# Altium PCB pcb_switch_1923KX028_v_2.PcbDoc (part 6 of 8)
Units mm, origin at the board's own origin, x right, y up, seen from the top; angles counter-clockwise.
Board outline 297.2 x 112.05 mm, 6 copper layers (Component Side, GND Layer 1, Inner Layer 1, Inner Layer 2, GND Layer 2, Solder Side), stack 1.578 mm thick; 545 components, 377 nets, 3174 pads, 1537 vias.
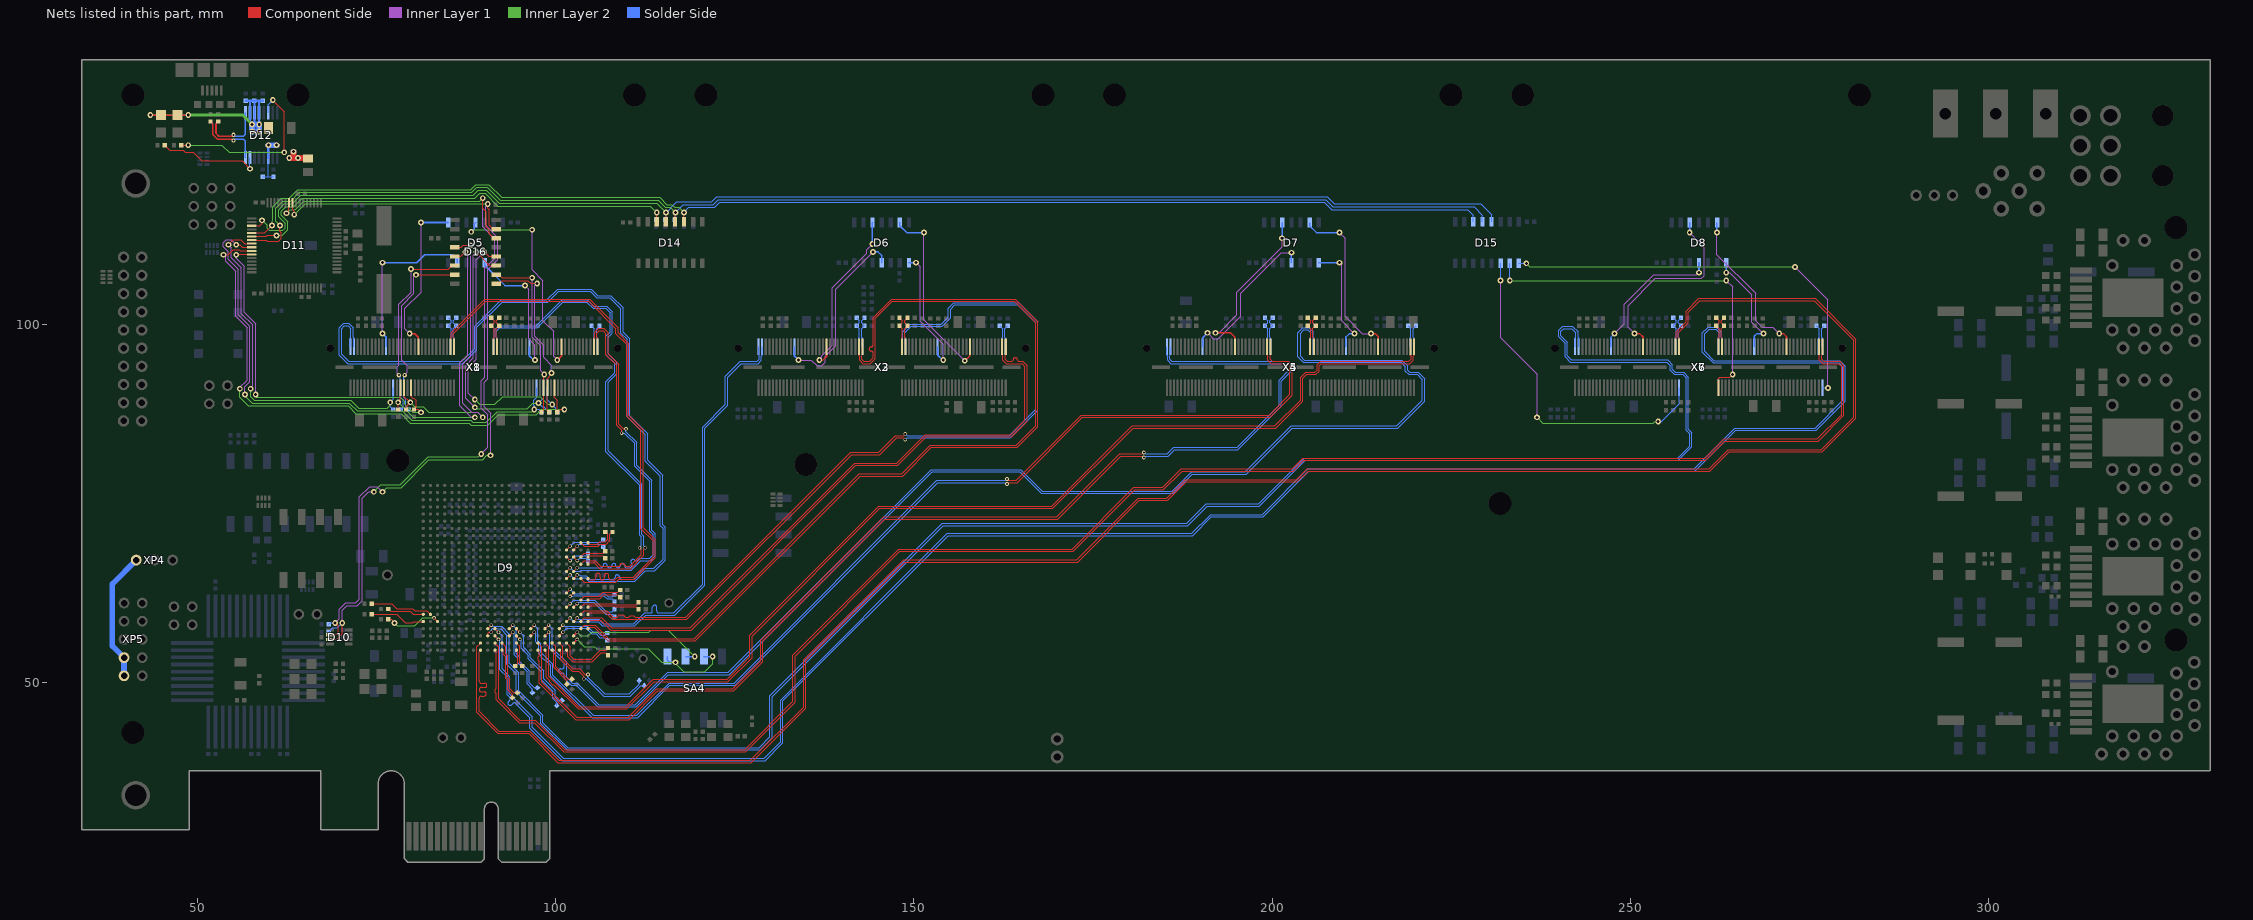
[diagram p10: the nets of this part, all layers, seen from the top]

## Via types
v1: diameter 0.8, hole 0.4, Component Side to Solder Side, tented both sides, 884 vias
v2: diameter 0.5, hole 0.3, Component Side to Solder Side, tented both sides, 269 vias
v3: diameter 1, hole 0.6, Component Side to Solder Side, tented both sides, 95 vias
v4: diameter 0.5/0.5/0.3/0.3/0.5/0.5 (per signal layer), hole 0.3, Component Side to Solder Side, tented both sides, 80 vias
v5: diameter 0.5/0.3/0.3/0.5/0.3/0.5 (per signal layer), hole 0.3, Component Side to Solder Side, tented both sides, 37 vias
v6: diameter 0.5/0.3/0.3/0.3/0.3/0.5 (per signal layer), hole 0.3, Component Side to Solder Side, tented both sides, 34 vias
v7: diameter 0.5/0.5/0.5/0.3/0.5/0.5 (per signal layer), hole 0.3, Component Side to Solder Side, tented both sides, 29 vias
v8: diameter 0.5, hole 0.3, Component Side to Solder Side, 25 vias
v9: diameter 0.5/0.3/0.5/0.3/0.3/0.5 (per signal layer), hole 0.3, Component Side to Solder Side, tented both sides, 25 vias
v10: diameter 0.5/0.5/0.3/0.5/0.5/0.5 (per signal layer), hole 0.3, Component Side to Solder Side, tented both sides, 19 vias
v11: diameter 0.6, hole 0.3, Component Side to Solder Side, tented both sides, 14 vias
v12: diameter 0.8, hole 0.5, Component Side to Solder Side, tented both sides, 11 vias
v13: diameter 0.5/0.3/0.5/0.5/0.3/0.5 (per signal layer), hole 0.3, Component Side to Solder Side, tented both sides, 7 vias
v14: diameter 0.8, hole 0.4, Component Side to Solder Side, 5 vias
v15: diameter 0.5/0.5/0.5/0.5/0.5/0.5 (per signal layer), hole 0.3, Component Side to Solder Side, tented both sides, 2 vias
v16: diameter 0.8, hole 0.5, Component Side to Solder Side, 1 vias

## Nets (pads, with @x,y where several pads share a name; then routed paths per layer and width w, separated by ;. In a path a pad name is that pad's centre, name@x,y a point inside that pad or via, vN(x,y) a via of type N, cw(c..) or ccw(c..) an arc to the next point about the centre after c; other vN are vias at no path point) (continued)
PHY_14_RST#: D15.3 X7.61 | length 47.1
  Inner Layer 1 w0.15: v1(231.9,106.1) 231.9,98.1 237,93 v1(237,87)
  Inner Layer 2 w0.15: v1(237,87) 237.8,86.2 253.2,86.2 253.419,86.419 v1(253.9,86.419)
  Solder Side w0.15: v1(231.9,106.1) 231.9,108.495 D15.3@231.905,108.5 ; v1(253.9,86.419) 254.319,86.419 256.81,88.91 X7.61@256.81,91.135
PHY_15_RST#: D15.2 X6.61 | length 49.6
  Component Side w0.15: X6.61@262.32,91.135 262.32,92.42 262.5,92.6 263.9,92.6 v1(264.3,93)
  Inner Layer 1 w0.15: v1(263.4,106.1) 264.3,105.2 v1(264.3,93)
  Inner Layer 2 w0.15: v1(233.2,106.1) v1(263.4,106.1)
  Solder Side w0.15: v1@233.175,106.125 D15.2@233.175,108.5
PHY_16_RST#: D15.1 X7.1 | length 58.4
  Inner Layer 1 w0.15: v1(273,108) 277.6,103.4 v1(277.6,91.1)
  Inner Layer 2 w0.15: v1(235.5,108.5) 236,108 v1(273,108)
  Solder Side w0.15: D15.1@234.445,108.5 v1(235.5,108.5) ; X7.1@276.815,91.135 276.85,91.1 v1(277.6,91.1)
PROG_3.3V: XP4.1 XP5.1 XP5.3 | length 18.2
  Solder Side w0.8: XP5.1@39.73,50.92 XP5.3@39.73,53.46 38.1,55.09 38.1,63.75 XP4.1@41.43,67.08
RCLK: D11.55 D14.12 D15.12 R119.2 | length 185
  Component Side w0.15: D11.55@57.55,111.75 59.55,111.75 59.7,111.6 61.3,111.6 61.7,112 61.7,112.8 61.5,113 v1(61.5,113.8) ; D14.12@116.635,114.3 116.7,114.365 v1(116.7,115.6)
  Inner Layer 2 w0.15: v1(61.5,113.8) 60.9,114.4 60.9,116.2 61.9,117.2 63,117.2 64.2,118.4 88.3,118.4 89,119.1 90.466,119.1 92.266,117.3 114.3,117.3 115.3,116.3 116,116.3 v1(116.7,115.6)
  Solder Side w0.15: R119.2@116.6,114.6 116.7,114.7 v1(116.7,115.6) 117.8,116.7 122,116.7 122.7,117.4 207.5,117.4 208.5,116.4 228.2,116.4 229.365,115.235 D15.12@229.365,114.3
RXLED#: D12.14 R11.2 | length 24.8
  Component Side w0.15: R11.2@47.7,125 v1(48.7,125) ; v1(60.5,131.3) 62.1,129.7 v1(62.1,124)
  Inner Layer 2 w0.15: v1(48.7,125) 53.4,125 54.4,124 v1(62.1,124)
  Solder Side w0.15: D12.14@59.852,129.524 59.852,130.653 v1(60.5,131.3)
SCL: D10.7 D11.42 D16.14 R176.1 | length 119
  Component Side w0.15: v1(62.4,115.5) 62.75,115.85 D11.42@62.75,116.95 ; D10.7@68.5,56 69.4,56 70.2,56.8 v1(70.2,58.3) ; v1(89.8,117.6) 89.8,116.2 90.3,115.7 90.3,113.6 90.7,113.2 90.7,112.6 91.295,112.005 D16.14@91.7,112.005
  Inner Layer 1 w0.15: v1(70.2,58.3) 70.2,60.1 70.8,60.7 72.3,60.7 73,61.4 73,75.7 73.9,76.6 v1(74.6,76.6) ; v1(89.6,81.9) 90.5,82.8 90.5,87.4 89.6,88.3 89.6,92.1 90.1,92.6 90.1,107.8 91.5,109.2 91.5,111.9 89.8,113.6 v1(89.8,117.6)
  Inner Layer 2 w0.15: v1(62.4,115.5) 62.9,116 63.6,116 64.8,117.2 89.4,117.2 v1(89.8,117.6) ; v1(74.6,76.6) 75.6,77.6 78.3,77.6 82.2,81.5 89.2,81.5 v1(89.6,81.9)
  Solder Side w0.15: R176.1@68.3,57 68.9,57.6 69.5,57.6 v1(70.2,58.3)
SDA: D10.6 D11.41 D16.15 R177.1 | length 115.6
  Component Side w0.15: D11.41@63.25,116.95 63.25,116 63.5,115.75 v1(63.5,115.3) ; D10.6@68.5,56.65 69.35,56.65 69.6,56.9 69.6,57.9 v1(69.2,58.3) ; v1(90.5,116.8) 90.5,116.2 90.7,116 90.7,113.8 91.225,113.275 D16.15@91.7,113.275
  Inner Layer 1 w0.15: v1(69.2,58.3) 69.8,58.9 69.8,60.2 70.7,61.1 72.1,61.1 72.6,61.6 72.6,75.9 74,77.3 75.1,77.3 v1(75.8,76.6) ; v1(90.5,116.8) 90.2,116.5 90.2,113.8 91.9,112.1 91.9,109 90.5,107.6 90.5,92.4 90,91.9 90,88.5 90.9,87.6 v1(90.9,81.7)
  Inner Layer 2 w0.15: v1(63.5,115.3) 65,116.8 v1(90.5,116.8) ; v1(75.8,76.6) 76.4,77.2 78.4,77.2 82.3,81.1 89.8,81.1 90.4,81.7 v1(90.9,81.7)
  Solder Side w0.15: R177.1@68.3,58.1 68.5,58.3 v1(69.2,58.3)
SGMII_L0DATI_0_N: C81.2 D9.J23 | length 5.9
  Component Side w0.15: D9.J23@103.5,69.5 104.01,68.99 105.928,68.99 106.238,69.3 107.038,69.3 107.565,69.827 107.565,70.655 C81.2@107.91,71
SGMII_L0DATI_0_P: C80.2 D9.J24 | length 4.3
  Component Side w0.15: D9.J24@104.5,69.5 104.7,69.3 105.8,69.3 106.11,69.61 106.91,69.61 107.255,69.955 107.255,70.655 C80.2@106.91,71
SGMII_L0DATI_1_N: C84.2 D9.K21 | length 5.7
  Component Side w0.15: D9.K21@101.5,68.5 v5(102,69)
  Solder Side w0.15: v5(102,69) 102.562,69.562 106.289,69.562 C84.2@106.629,69.902
SGMII_L0DATI_1_P: C82.2 D9.K22 | length 4.6
  Component Side w0.15: D9.K22@102.5,68.5 v5(103,69)
  Solder Side w0.15: v5(103,69) 103.252,69.252 106.289,69.252 C82.2@106.629,68.912
SGMII_L0DATI_2_N: C185.2 D9.L23 | length 3.7
  Component Side w0.15: D9.L23@103.5,67.5 104.01,68.01 105.11,68.01 106.585,68.01 C185.2@106.9,68.325
SGMII_L0DATI_2_P: C186.2 D9.L24 | length 2.6
  Component Side w0.15: D9.L24@104.5,67.5 104.7,67.7 106.525,67.7 C186.2@106.9,67.325
SGMII_L0DATI_3_N: C191.2 D9.L21 | length 3.6
  Component Side w0.15: D9.L21@101.5,67.5 v6(102,67)
  Solder Side w0.15: v6(102,67) 102.655,67.655 104.155,67.655 C191.2@104.5,68
SGMII_L0DATI_3_P: C192.2 D9.L22 | length 2.5
  Component Side w0.15: D9.L22@102.5,67.5 v6(103,67)
  Solder Side w0.15: v6(103,67) 103.345,67.345 104.155,67.345 C192.2@104.5,67
SGMII_L0DATO_0_N: D9.P23 X1.58 | length 75.2
  Component Side w0.15: X1.58@85.315,96.865 85.315,98.09 85.41,98.185 85.41,98.828 90.082,103.5 104.738,103.5 108.71,99.528 108.71,98.8 110.2,97.31 110.2,87.3 112.2,85.3 112.2,71.6 113.91,69.89 113.91,67.372 110.928,64.39 108.79,64.39 108.39,63.99 104.01,63.99 D9.P23@103.5,64.5
SGMII_L0DATO_0_P: D9.P24 X1.60 | length 75.2
  Component Side w0.15: X1.60@85.815,96.865 85.815,98.09 85.72,98.185 85.72,98.7 90.21,103.19 104.61,103.19 108.4,99.4 108.4,98.672 109.89,97.182 109.89,87.172 111.89,85.172 111.89,71.472 113.6,69.762 113.6,67.5 110.8,64.7 108.662,64.7 108.262,64.3 107.7,64.3 cw(c107.7,64.6) 107.4,64.6 107.4,64.9 ccw(c107.1,64.9) 106.8,64.9 106.8,64.6 cw(c106.5,64.6) 106.5,64.3 cw(c106.5,64.6) 106.2,64.6 106.2,64.95 ccw(c105.9,64.95) 105.6,64.95 105.6,64.6 cw(c105.3,64.6) 105.3,64.3 104.7,64.3 D9.P24@104.5,64.5
SGMII_L0DATO_1_N: D9.P22 X8.118 | length 108
  Component Side w0.15: D9.P22@102.5,64.5 v6(103,65)
  Solder Side w0.15: X8.118@71.81,96.865 71.81,98.09 71.715,98.185 71.715,99.523 71.128,100.11 70.372,100.11 69.79,99.528 69.79,95.672 70.972,94.49 87.028,94.49 89,96.462 89,99.562 92.538,103.1 98.9,103.1 100.4,104.6 104.8,104.6 105.7,103.7 107.562,103.7 109.1,102.162 109.1,98.762 109.99,97.872 109.99,87.11 112.5,84.6 112.5,80.9 114.6,78.8 114.6,71.9 115,71.5 115,67.2 113.71,65.91 112.372,65.91 110.872,64.41 109.2,64.41 cw(c109.2,64.71) 108.9,64.71 108.9,64.714 ccw(c108.6,64.714) 108.3,64.714 108.3,64.71 cw(c108,64.71) 108,64.41 104.723,64.41 104.228,64.905 103.395,64.905 103.3,65 v6(103,65)
SGMII_L0DATO_1_P: D9.P21 X8.120 | length 108
  Component Side w0.15: D9.P21@101.5,64.5 v6(102,65)
  Solder Side w0.15: X8.120@71.31,96.865 71.31,98.09 71.405,98.185 71.405,99.395 71,99.8 70.5,99.8 70.1,99.4 70.1,95.8 71.1,94.8 86.9,94.8 88.69,96.59 88.69,99.69 92.41,103.41 98.772,103.41 100.272,104.91 104.928,104.91 105.828,104.01 107.69,104.01 109.41,102.29 109.41,98.89 110.3,98 110.3,87.238 112.81,84.728 112.81,81.028 114.91,78.928 114.91,72.028 115.31,71.628 115.31,67.072 113.838,65.6 112.5,65.6 111,64.1 104.595,64.1 104.1,64.595 103.395,64.595 103.3,64.5 102.5,64.5 v6(102,65)
SGMII_L0DATO_2_N: D9.N21 X1.118 | length 52.2
  Component Side w0.15: D9.N21@101.5,65.5 v6(102,66) ; X1.118@105.32,96.865 105.32,98.09 105.415,98.185 105.415,98.853 105.972,99.41 106.728,99.41 107.31,98.828 107.31,95.9 108.8,94.41 108.8,86.019 109.419,85.4 v8(109.8,85.4)
  Solder Side w0.15: v6(102,66) 102.5,65.5 103.4,65.5 103.59,65.69 110.528,65.69 111.838,67 113.238,67 113.91,67.672 113.91,70.728 113.41,71.228 113.41,78.228 111.31,80.328 111.31,83.509 109.8,85.019 v8(109.8,85.4)
SGMII_L0DATO_2_P: D9.N22 X1.120 | length 52.2
  Component Side w0.15: D9.N22@102.5,65.5 v6(103,66) ; X1.120@105.82,96.865 105.82,98.09 105.725,98.185 105.725,98.725 106.1,99.1 106.6,99.1 107,98.7 107,95.772 108.49,94.282 108.49,85.891 109.2,85.181 v8(109.2,84.8)
  Solder Side w0.15: v6(103,66) 106.3,66 ccw(c106.3,66.3) 106.6,66.3 cw(c106.9,66.3) 106.9,66.6 cw(c106.9,66.3) 107.2,66.3 ccw(c107.5,66.3) 107.5,66 ccw(c107.5,66.3) 107.8,66.3 cw(c108.1,66.3) 108.1,66.6 cw(c108.1,66.3) 108.4,66.3 ccw(c108.7,66.3) 108.7,66 ccw(c108.7,66.3) 109,66.3 cw(c109.3,66.3) 109.3,66.6 cw(c109.3,66.3) 109.6,66.3 ccw(c109.9,66.3) 109.9,66 110.4,66 110.6,66.2 ccw(c110.388,66.412) 110.6,66.624 110.57,66.654 cw(c110.782,66.866) 110.57,67.079 cw(c110.782,66.866) 110.994,67.079 111.024,67.049 ccw(c111.236,67.261) 111.449,67.049 111.71,67.31 113.11,67.31 113.6,67.8 113.6,70.6 113.1,71.1 113.1,78.1 111,80.2 111,83.381 109.581,84.8 v8(109.2,84.8)
SGMII_L0DATO_3_N: D9.M23 X8.58 | length 67.7
  Component Side w0.15: D9.M23@103.5,66.5 104.01,67.01 105.49,67.01 106.29,66.21 108.82,66.21 ccw(c108.82,66.4) 109.01,66.4 cw(c109.184,66.4) 109.184,66.574 109.436,66.574 cw(c109.436,66.4) 109.61,66.4 ccw(c109.8,66.4) 109.8,66.21 110.31,66.21 111.945,67.845 111.945,68.555 v8(111.7,68.8)
  Solder Side w0.15: X8.58@91.815,96.865 91.815,98.09 91.72,98.185 91.72,99.02 92.2,99.5 97.4,99.5 101,103.1 104.3,103.1 105.2,102.2 107,102.2 107.6,101.6 107.6,98.9 107,98.3 107,95.762 108.2,94.562 108.2,93.2 107,92 107,82.2 111.7,77.5 111.7,70.545 111.945,70.3 111.945,69.045 v8(111.7,68.8)
SGMII_L0DATO_3_P: D9.M24 X8.60 | length 67.7
  Component Side w0.15: D9.M24@104.5,66.5 104.7,66.7 105.362,66.7 106.162,65.9 110.438,65.9 112.255,67.717 112.255,68.555 v8(112.5,68.8)
  Solder Side w0.15: X8.60@91.315,96.865 91.315,98.09 91.41,98.185 91.41,99.148 92.072,99.81 97.272,99.81 100.872,103.41 104.428,103.41 105.328,102.51 107.128,102.51 107.91,101.728 107.91,98.772 107.31,98.172 107.31,95.89 108.51,94.69 108.51,93.072 107.31,91.872 107.31,82.328 112.01,77.628 112.01,70.673 112.255,70.428 112.255,69.045 v8(112.5,68.8)
SGMII_L1DATI_0_N: C89.2 D9.T21 | length 7.5
  Component Side w0.15: D9.T21@101.5,62.5 v6(102,63)
  Solder Side w0.15: v6@102,63 102.595,62.405 106.85,62.405 107.3,61.955 107.855,61.955 C89.2@108.2,62.3
SGMII_L1DATI_0_P: C87.2 D9.T22 | length 7.3
  Component Side w0.15: v6(102,62) D9.T22@102.5,62.5
  Solder Side w0.15: v6(102,62) 102.4,62 102.495,62.095 106.722,62.095 107.172,61.645 107.855,61.645 C87.2@108.2,61.3
SGMII_L1DATI_1_N: C62.2 D9.V23 | length 8.5
  Component Side w0.15: D9.V23@103.5,60.5 104.01,61.01 108.19,61.01 108.357,60.843 111.219,60.843 C62.2@111.559,61.183
SGMII_L1DATI_1_P: C60.2 D9.V24 | length 7.4
  Component Side w0.15: D9.V24@104.5,60.5 104.7,60.7 108.062,60.7 108.229,60.533 111.219,60.533 C60.2@111.559,60.193
SGMII_L1DATI_2_N: C93.2 D9.U23 | length 6.1
  Component Side w0.15: D9.U23@103.5,61.5 104.01,62.01 106.005,62.01 106.55,62.555 108.655,62.555 C93.2@109,62.9
SGMII_L1DATI_2_P: C91.2 D9.U24 | length 5
  Component Side w0.15: D9.U24@104.5,61.5 104.7,61.7 106.133,61.7 106.678,62.245 108.655,62.245 C91.2@109,61.9
SGMII_L1DATI_3_N: C68.2 D9.V21 | length 7.9
  Component Side w0.15: D9.V21@101.5,60.5 v6(102,61)
  Solder Side w0.15: v6(102,61) 102.5,61.5 105.428,61.5 107.073,59.855 107.855,59.855 C68.2@108.2,60.2
SGMII_L1DATI_3_P: C67.2 D9.V22 | length 6.8
  Component Side w0.15: D9.V22@102.5,60.5 v6(103,61)
  Solder Side w0.15: v6(103,61) 103.19,61.19 105.3,61.19 106.945,59.545 107.855,59.545 C67.2@108.2,59.2
SGMII_L1DATO_0_N: D9.AA23 X2.58 | length 126.1
  Component Side w0.15: D9.AA23@103.5,57.5 104.01,58.01 105.49,58.01 107.39,56.11 119.362,56.11 142.362,79.11 148.31,79.11 152.31,83.11 164.31,83.11 167,85.8 167,100.2 164,103.2 147,103.2 144.61,100.81 144.61,95.172 143.928,94.49 142.892,94.49 142.41,94.972 142.41,95.545 142.315,95.64 X2.58@142.315,96.865
SGMII_L1DATO_0_P: D9.AA24 X2.60 | length 126.1
  Component Side w0.15: D9.AA24@104.5,57.5 104.7,57.7 105.362,57.7 107.262,55.8 119.49,55.8 142.49,78.8 148.438,78.8 152.438,82.8 164.438,82.8 167.31,85.672 167.31,100.328 164.128,103.51 146.872,103.51 144.3,100.938 144.3,97.1 cw(c144.05,97.1) 144.05,96.85 144.028,96.85 ccw(c144.028,96.6) 143.778,96.6 143.778,96.5 ccw(c144.028,96.5) 144.028,96.25 144.05,96.25 cw(c144.05,96) 144.3,96 144.3,95.3 143.8,94.8 143.02,94.8 142.72,95.1 142.72,95.545 142.815,95.64 X2.60@142.815,96.865
SGMII_L1DATO_1_N: D9.Y21 X3.118 | length 60.3
  Component Side w0.15: D9.Y21@101.5,58.5 v6(102,59)
  Solder Side w0.15: v6(102,59) 102.4,58.6 102.51,58.49 105.9,58.49 106.49,57.9 111.038,57.9 112.528,59.39 116.628,59.39 120.82,63.582 120.82,85.492 124,88.672 124,92.6 125.89,94.49 128.233,94.49 128.715,94.972 128.715,95.545 128.81,95.64 X3.118@128.81,96.865
SGMII_L1DATO_1_P: D9.Y22 X3.120 | length 60.3
  Component Side w0.15: D9.Y22@102.5,58.5 v6(103,59)
  Solder Side w0.15: v6(103,59) 103.2,58.8 106.028,58.8 106.618,58.21 110.91,58.21 112.4,59.7 113.2,59.7 ccw(c113.2,60) 113.5,60 113.5,60.478 cw(c113.8,60.478) 113.8,60.778 cw(c113.8,60.478) 114.1,60.478 114.1,60 ccw(c114.4,60) 114.4,59.7 116.5,59.7 120.51,63.71 120.51,85.62 123.69,88.8 123.69,92.728 125.762,94.8 128.105,94.8 128.405,95.1 128.405,95.545 128.31,95.64 X3.120@128.31,96.865
SGMII_L1DATO_2_N: D9.Y23 X2.118 | length 87.7
  Component Side w0.15: D9.Y23@103.5,58.5 104.01,59.01 106.423,59.01 107.823,57.61 118.772,57.61 141.772,80.61 147.61,80.61 151.6,84.6 163.5,84.6 165.5,86.6 165.5,94.09 165.1,94.49 162.897,94.49 162.415,94.972 162.415,95.545 162.32,95.64 X2.118@162.32,96.865
SGMII_L1DATO_2_P: D9.Y24 X2.120 | length 87.7
  Component Side w0.15: D9.Y24@104.5,58.5 104.7,58.7 106.295,58.7 107.695,57.3 118.9,57.3 141.9,80.3 147.738,80.3 151.728,84.29 163.628,84.29 165.81,86.472 165.81,94.218 165.228,94.8 164.7,94.8 cw(c164.7,95.05) 164.45,95.05 164.45,95.072 ccw(c164.2,95.072) 164.2,95.322 164.1,95.322 ccw(c164.1,95.072) 163.85,95.072 163.85,95.05 cw(c163.6,95.05) 163.6,94.8 163.025,94.8 162.725,95.1 162.725,95.545 162.82,95.64 X2.120@162.82,96.865
SGMII_L1DATO_3_N: D9.W23 X3.58 | length 112.5
  Component Side w0.15: D9.W23@103.5,59.5 104.01,60.01 107.127,60.01 108.027,59.11 108.58,59.11 108.89,59.42 109.39,59.42 109.7,59.11 110.2,59.11 110.39,59.3 110.89,59.3 111.08,59.11 118.172,59.11 141.172,82.11 145.11,82.11 147.4,84.4 ; 147.364,84.364 147.455,84.455 148.555,84.455 v8(148.8,84.7)
  Solder Side w0.15: v8(148.8,84.7) 149.045,84.455 163.317,84.455 167,88.138 167,100.2 164.5,102.7 155.71,102.7 155.11,102.1 155.11,100.882 153.928,99.7 149.62,99.7 148.72,98.8 148.72,98.185 148.815,98.09 X3.58@148.815,96.865
SGMII_L1DATO_3_P: D9.W24 X3.60 | length 112.4
  Component Side w0.15: D9.W24@104.5,59.5 104.7,59.7 106.999,59.7 107.899,58.8 118.3,58.8 141.3,81.8 145.238,81.8 147.583,84.145 148.555,84.145 v8(148.8,83.9)
  Solder Side w0.15: X3.60@148.315,96.865 148.315,98.09 148.41,98.185 148.41,98.928 149.492,100.01 153.8,100.01 154.8,101.01 154.8,102.228 155.582,103.01 164.628,103.01 167.31,100.328 167.31,88.01 163.445,84.145 149.045,84.145 v8(148.8,83.9)
SGMII_L2DATI_0_N: C79.2 D9.AC21 | length 8.2
  Component Side w0.15: D9.AC21@101.5,55.5 102.01,54.99 102.01,53.7 102.51,53.2 104.962,53.2 106.217,54.455 106.955,54.455 C79.2@107.3,54.8
SGMII_L2DATI_0_P: C77.2 D9.AD21 | length 7.6
  Component Side w0.15: D9.AD21@101.5,54.5 101.7,54.3 101.7,53.572 102.382,52.89 105.09,52.89 106.345,54.145 106.955,54.145 C77.2@107.3,53.8
SGMII_L2DATI_1_N: C73.2 D9.AA20 | length 7.6
  Component Side w0.15: D9.AA20@100.5,57.5 v6(101,58)
  Solder Side w0.15: v6(101,58) 101.165,57.835 104.403,57.835 105.138,57.1 105.755,57.1 106.3,56.555 106.855,56.555 C73.2@107.2,56.9
SGMII_L2DATI_1_P: C72.2 D9.AB20 | length 7.8
  Component Side w0.15: D9.AB20@100.5,56.5 v6(101,57)
  Solder Side w0.15: v6(101,57) 101.525,57.525 104.275,57.525 105.01,56.79 105.627,56.79 106.172,56.245 106.855,56.245 C72.2@107.2,55.9
SGMII_L2DATI_2_N: C97.2 D9.AC20 | length 16.3
  Component Side w0.15: D9.AC20@100.5,55.5 101.01,54.99 101.01,54.19 101.01,53.295 102.405,51.9 103.319,51.9 104.119,51.1 v8(104.5,51.1)
  Solder Side w0.15: v8(104.5,51.1) 104.5,50.719 106.819,48.4 110.281,48.4 111.646,49.766 C97.2@111.646,50.246
SGMII_L2DATI_2_P: C98.2 D9.AD20 | length 16
  Component Side w0.15: D9.AD20@100.5,54.5 100.7,54.3 100.7,53.167 102.277,51.59 103.191,51.59 103.9,50.881 v8(103.9,50.5)
  Solder Side w0.15: v8(103.9,50.5) 104.281,50.5 106.691,48.09 110.409,48.09 111.866,49.546 C98.2@112.346,49.546
SGMII_L2DATI_3_N: C64.2 D9.AC19 | length 6.5
  Component Side w0.15: D9.AC19@99.5,55.5 100.01,54.99 100.01,52.209 101.766,50.454 C64.2@102.246,50.454
SGMII_L2DATI_3_P: C76.2 D9.AD19 | length 5.6
  Component Side w0.15: D9.AD19@99.5,54.5 99.7,54.3 99.7,52.081 101.546,50.234 C76.2@101.546,49.754
SGMII_L2DATO_0_N: D9.AA16 X4.58 | length 142
  Component Side w0.15: D9.AA16@96.5,57.5 v6(97,58) ; v8(163,78.4) 163.195,78.205 164.3,78.205 173.395,87.3 199.6,87.3 202.5,90.2 202.5,94.09 202.1,94.49 199.892,94.49 199.41,94.972 199.41,95.545 199.315,95.64 X4.58@199.315,96.865
  Solder Side w0.15: v6(97,58) 97.5,57.5 97.5,55.8 97.91,55.39 97.91,54.2 99.61,52.5 99.61,50.99 105.2,45.4 111.3,45.4 115.81,49.91 124.9,49.91 153.195,78.205 162.805,78.205 v8(163,78.4)
SGMII_L2DATO_0_P: D9.AB16 X4.60 | length 142
  Component Side w0.15: D9.AB16@96.5,56.5 v6(97,57) ; v8(163,77.7) 163.195,77.895 164.428,77.895 173.523,86.99 199.728,86.99 202.81,90.072 202.81,94.218 202.228,94.8 200.02,94.8 199.72,95.1 199.72,95.545 199.815,95.64 X4.60@199.815,96.865
  Solder Side w0.15: v6(97,57) 97.19,56.81 97.19,55.672 97.6,55.262 97.6,54.072 98,53.672 98,53.498 98.361,53.137 98.535,53.137 99.3,52.372 99.3,50.862 105.072,45.09 111.428,45.09 115.938,49.6 125.028,49.6 153.323,77.895 162.805,77.895 v8(163,77.7)
SGMII_L2DATO_1_N: D9.AD17 X5.118 | length 156.1
  Component Side w0.15: D9.AD17@97.5,54.5 97.7,54.3 97.7,53.7 97.58,53.58 97.58,53.08 97.7,52.96 97.7,49.862 102.772,44.79 110.228,44.79 114.238,48.8 124.838,48.8 128.91,52.872 128.91,55.772 145.938,72.8 170.1,72.8 178.895,81.595 181.905,81.595 v8(182.1,81.4)
  Solder Side w0.15: v8(182.1,81.4) 182.295,81.595 185.505,81.595 186.41,82.5 195.238,82.5 201.31,88.572 201.31,92.072 202.81,93.572 202.81,94.228 202.238,94.8 186.015,94.8 185.715,95.1 185.715,95.545 185.81,95.64 X5.118@185.81,96.865
SGMII_L2DATO_1_P: D9.AC17 X5.120 | length 156.1
  Component Side w0.15: D9.AC17@97.5,55.5 98.01,54.99 98.01,49.99 102.9,45.1 110.1,45.1 114.11,49.11 124.71,49.11 128.6,53 128.6,55.9 145.81,73.11 169.972,73.11 178.767,81.905 181.905,81.905 v8(182.1,82.1)
  Solder Side w0.15: v8(182.1,82.1) 182.295,81.905 185.377,81.905 186.282,82.81 195.11,82.81 201,88.7 201,92.2 202.5,93.7 202.5,94.1 202.11,94.49 185.887,94.49 185.405,94.972 185.405,95.545 185.31,95.64 X5.120@185.31,96.865
SGMII_L2DATO_2_N: D9.AC18 X4.118 | length 153
  Component Side w0.15: D9.AC18@98.5,55.5 99.01,54.99 99.01,50.828 103.238,46.6 109.8,46.6 113.61,50.41 123.91,50.41 127.1,53.6 127.1,56.6 145.11,74.61 169.272,74.61 180.462,85.8 200.4,85.8 203.99,89.39 203.99,92.59 204.7,93.3 205.99,93.3 206.29,93.6 206.29,94.318 206.772,94.8 219.115,94.8 219.415,95.1 219.415,95.545 219.32,95.64 X4.118@219.32,96.865
SGMII_L2DATO_2_P: D9.AD18 X4.120 | length 153
  Component Side w0.15: D9.AD18@98.5,54.5 98.7,54.3 98.7,50.7 99.165,50.235 99.165,50.061 99.526,49.7 99.7,49.7 103.11,46.29 109.928,46.29 113.738,50.1 124.038,50.1 127.41,53.472 127.41,56.472 145.238,74.3 169.4,74.3 180.59,85.49 200.528,85.49 204.3,89.262 204.3,92.462 204.828,92.99 206.118,92.99 206.6,93.472 206.6,94.19 206.9,94.49 219.243,94.49 219.725,94.972 219.725,95.545 219.82,95.64 X4.120@219.82,96.865
SGMII_L2DATO_3_N: D9.AA18 X5.58 | length 180.3
  Component Side w0.15: D9.AA18@98.5,57.5 v6(99,58)
  Solder Side w0.15: v6(99,58) 99.5,57.5 99.5,54.8 101.5,52.8 101.5,50.7 102.3,49.9 103,49.9 106,46.9 111.1,46.9 115.6,51.4 124.09,51.4 152.4,79.71 164.89,79.71 167.9,76.7 186.062,76.7 188.762,79.4 196.272,79.4 202.672,85.8 217.4,85.8 221,89.4 221,92.262 220.272,92.99 219.082,92.99 218.6,93.472 218.6,94.09 218,94.69 204.372,94.69 203.59,95.472 203.59,98.828 204.272,99.51 205.138,99.51 205.72,98.928 205.72,98.185 205.815,98.09 X5.58@205.815,96.865
SGMII_L2DATO_3_P: D9.AB18 X5.60 | length 180.3
  Component Side w0.15: D9.AB18@98.5,56.5 v6(99,57)
  Solder Side w0.15: v6(99,57) 99.19,56.81 99.19,54.672 101.19,52.672 101.19,52.2 cw(c100.89,52.2) 100.89,51.9 100.668,51.9 ccw(c100.668,51.6) 100.368,51.6 ccw(c100.668,51.6) 100.668,51.3 100.89,51.3 cw(c100.89,51) 101.19,51 101.19,50.572 102.172,49.59 102.872,49.59 105.872,46.59 111.228,46.59 115.728,51.09 124.218,51.09 152.528,79.4 164.762,79.4 167.772,76.39 186.19,76.39 188.89,79.09 196.4,79.09 202.8,85.49 217.528,85.49 221.31,89.272 221.31,92.39 220.4,93.3 219.21,93.3 218.91,93.6 218.91,94.218 218.128,95 216.7,95 204.5,95 203.9,95.6 203.9,98.7 204.4,99.2 205.01,99.2 205.41,98.8 205.41,98.185 205.315,98.09 X5.60@205.315,96.865
SGMII_L3DATI_0_N: C49.2 D9.AC14 | length 3.5
  Component Side w0.15: D9.AC14@94.5,55.5 94.98,55.02 94.98,52.645 C49.2@95.325,52.3
SGMII_L3DATI_0_P: C48.2 D9.AD14 | length 2.4
  Component Side w0.15: C48.2@94.325,52.3 94.67,52.645 94.67,54.23 94.5,54.4 D9.AD14@94.5,54.5
SGMII_L3DATI_1_N: C55.2 D9.AA14 | length 13
  Component Side w0.15: D9.AA14@94.5,57.5 v6(95,57)
  Solder Side w0.15: v6(95,57) 95.5,56.5 95.5,54.9 96.46,53.94 96.46,53.44 98.3,51.6 98.3,51.472 ; 98.3,51.5 98.3,50.5 99.9,48.9 99.9,47.919 100.366,47.454 C55.2@100.846,47.454
SGMII_L3DATI_1_P: C54.2 D9.AB14 | length 12.1
  Component Side w0.15: D9.AB14@94.5,56.5 v6(95,56)
  Solder Side w0.15: v6(95,56) 95.19,55.81 95.19,54.772 96.15,53.812 96.15,53.312 97.99,51.472 97.99,50.372 99.59,48.772 99.59,47.791 100.146,47.234 C54.2@100.146,46.754
SGMII_L3DATI_2_N: C88.2 D9.AA13 | length 11.2
  Component Side w0.15: D9.AA13@93.5,57.5 v6(94,58)
  Solder Side w0.15: v6(94,58) 94.5,57.5 94.5,54 95,53.5 95,52.9 96.3,51.6 96.3,49.919 96.966,49.254 C88.2@97.446,49.254
SGMII_L3DATI_2_P: C86.2 D9.AB13 | length 10.3
  Component Side w0.15: D9.AB13@93.5,56.5 v6(94,57)
  Solder Side w0.15: v6(94,57) 94.19,56.81 94.19,53.872 94.69,53.372 94.69,52.772 95.99,51.472 95.99,49.791 96.746,49.034 C86.2@96.746,48.554
SGMII_L3DATI_3_N: C92.2 D9.AC12 | length 8.1
  Component Side w0.15: D9.AC12@92.5,55.5 93.01,54.99 93.01,54.028 93.31,53.728 93.31,50.7 93.61,50.4 93.61,49.109 94.166,48.554 C92.2@94.646,48.554
SGMII_L3DATI_3_P: C90.2 D9.AD12 | length 7.2
  Component Side w0.15: D9.AD12@92.5,54.5 92.7,54.3 92.7,53.9 93,53.6 93,50.572 93.3,50.272 93.3,48.981 93.946,48.334 C90.2@93.946,47.854
SGMII_L3DATO_0_N: D9.AC9 X6.58 | length 272.5
  Component Side w0.15: D9.AC9@89.5,55.5 88.99,54.99 88.99,45.81 91.91,42.89 96.21,42.89 100.31,38.79 127.29,38.79 134.91,46.41 134.91,53.01 148.7,66.8 172.838,66.8 181.438,75.4 185.438,75.4 188.038,78 203.538,78 205.028,79.49 261.128,79.49 263.828,82.19 276.828,82.19 281.51,86.872 281.51,97.928 275.828,103.61 259.582,103.61 257.8,101.828 257.8,100.318 256.41,98.928 256.41,98.185 256.315,98.09 X6.58@256.315,96.865
SGMII_L3DATO_0_P: D9.AD9 X6.60 | length 272.5
  Component Side w0.15: D9.AD9@89.5,54.5 89.3,54.3 89.3,50.2 ccw(c89.6,50.2) 89.6,49.9 90.1,49.9 cw(c90.1,49.6) 90.4,49.6 cw(c90.1,49.6) 90.1,49.3 89.6,49.3 ccw(c89.6,49) 89.3,49 ccw(c89.6,49) 89.6,48.7 90.007,48.7 cw(c90.007,48.4) 90.306,48.4 cw(c90.007,48.4) 90.007,48.1 89.6,48.1 ccw(c89.6,47.8) 89.3,47.8 89.3,45.938 92.038,43.2 96.338,43.2 100.438,39.1 127.162,39.1 134.6,46.538 134.6,53.138 148.572,67.11 172.71,67.11 181.31,75.71 185.31,75.71 187.91,78.31 203.41,78.31 204.9,79.8 261,79.8 263.7,82.5 276.7,82.5 281.2,87 281.2,97.8 275.7,103.3 259.71,103.3 258.11,101.7 258.11,100.19 256.72,98.8 256.72,98.185 256.815,98.09 X6.60@256.815,96.865
SGMII_L3DATO_1_N: D9.AA10 X7.118 | length 238
  Component Side w0.15: D9.AA10@90.5,57.5 v6(91,58)
  Solder Side w0.15: v6(91,58) 91.19,57.81 92.428,57.81 93.5,56.738 93.5,52.638 94.81,51.328 94.81,48.828 98.21,45.428 98.21,44.39 101.7,40.9 128.4,40.9 129.9,42.4 129.9,48.138 153.972,72.21 188.11,72.21 190.81,74.91 198.11,74.91 204.51,81.31 256.61,81.31 258.3,83 258.3,84.7 257.8,85.2 257.8,92.5 257.31,92.99 256.172,92.99 255.59,93.572 255.59,94.2 255.09,94.7 241.662,94.7 240.9,95.462 240.9,97.362 239.99,98.272 239.99,99.128 240.572,99.71 241.933,99.71 242.715,98.928 242.715,98.185 242.81,98.09 X7.118@242.81,96.865
SGMII_L3DATO_1_P: D9.AB10 X7.120 | length 238
  Component Side w0.15: D9.AB10@90.5,56.5 90.5,56.775 cw(c90.725,56.775) 90.725,57 v6(91,57)
  Solder Side w0.15: v6(91,57) 91,57.25 cw(c91.25,57.25) 91.25,57.5 92.3,57.5 93.19,56.61 93.19,52.51 94.5,51.2 94.5,48.7 97.9,45.3 97.9,44.262 101.572,40.59 128.528,40.59 130.21,42.272 130.21,48.01 154.1,71.9 188.238,71.9 190.938,74.6 198.238,74.6 204.638,81 256.738,81 258.61,82.872 258.61,84.828 258.11,85.328 258.11,91.1 258.11,92.628 257.438,93.3 256.3,93.3 255.9,93.7 255.9,94.328 255.218,95.01 241.79,95.01 241.21,95.59 241.21,97.49 240.3,98.4 240.3,99 240.7,99.4 241.805,99.4 242.405,98.8 242.405,98.185 242.31,98.09 X7.120@242.31,96.865
SGMII_L3DATO_2_N: D9.AC11 X6.118 | length 233.7
  Component Side w0.15: D9.AC11@91.5,55.5 92.01,54.99 92.01,47.69 95,44.7 97.138,44.7 101.238,40.6 126.362,40.6 133.1,47.338 133.1,53.8 147.91,68.61 172.11,68.61 180.71,77.21 184.71,77.21 187.31,79.81 202.81,79.81 204.31,81.31 260.41,81.31 263.1,84 276.1,84 279.5,87.4 279.5,94.09 279.1,94.49 276.897,94.49 276.415,94.972 276.415,95.545 276.32,95.64 X6.118@276.32,96.865
SGMII_L3DATO_2_P: D9.AD11 X6.120 | length 233.7
  Component Side w0.15: D9.AD11@91.5,54.5 91.7,54.3 91.7,49.2 91.577,49.077 91.577,48.567 91.7,48.444 91.7,47.562 94.872,44.39 97.01,44.39 101.11,40.29 126.49,40.29 133.41,47.21 133.41,53.672 148.038,68.3 172.238,68.3 180.838,76.9 184.838,76.9 187.438,79.5 202.938,79.5 204.438,81 260.538,81 263.228,83.69 276.228,83.69 279.81,87.272 279.81,94.218 279.228,94.8 277.025,94.8 276.725,95.1 276.725,95.545 276.82,95.64 X6.120@276.82,96.865
SGMII_L3DATO_3_N: D9.AA11 X7.58 | length 258
  Component Side w0.15: D9.AA11@91.5,57.5 v6(92,57)
  Solder Side w0.15: v6(92,57) 92.5,56.5 92.5,51.9 93.51,50.89 93.51,48.39 96.71,45.19 96.71,43.728 101.038,39.4 129.1,39.4 131.4,41.7 131.4,47.538 154.672,70.81 188.81,70.81 191.41,73.41 198.61,73.41 205.01,79.81 258.91,79.81 264.61,85.51 275.81,85.51 279.69,89.39 279.69,94.01 279.1,94.6 261.562,94.6 260.09,96.072 260.09,98.828 260.872,99.61 262.038,99.61 262.72,98.928 262.72,98.185 262.815,98.09 X7.58@262.815,96.865
SGMII_L3DATO_3_P: D9.AB11 X7.60 | length 258
  Component Side w0.15: D9.AB11@91.5,56.5 v6(92,56)
  Solder Side w0.15: v6(92,56) 92.19,55.81 92.19,51.772 93.2,50.762 93.2,48.262 93.562,47.9 cw(c93.349,47.688) 93.562,47.476 93.405,47.319 ccw(c93.617,47.107) 93.405,46.895 ccw(c93.617,47.107) 93.829,46.895 93.986,47.051 cw(c94.198,46.839) 94.41,47.051 96.4,45.062 96.4,43.6 100.91,39.09 129.228,39.09 131.71,41.572 131.71,47.41 154.8,70.5 188.938,70.5 191.538,73.1 198.738,73.1 205.138,79.5 259.038,79.5 264.738,85.2 275.938,85.2 280,89.262 280,94.138 279.228,94.91 261.69,94.91 260.4,96.2 260.4,98.7 261,99.3 261.91,99.3 262.41,98.8 262.41,98.185 262.315,98.09 X7.60@262.315,96.865
SHIFT_REG_IN: D11.54 D14.14 R118.2 | length 65.3
  Component Side w0.15: D11.54@57.55,112.25 59.55,112.25 59.7,112.4 v1(61,112.4) ; D14.14@114.095,114.3 114.1,114.305 v1(114.1,115.6)
  Inner Layer 2 w0.15: v1(61,112.4) 61.8,112.4 62.6,113.2 62.6,114.3 61.7,115.2 61.7,115.8 62.3,116.4 63.4,116.4 64.6,117.6 88.7,117.6 89.4,118.3 90.134,118.3 91.934,116.5 113.2,116.5 v1(114.1,115.6)
  Solder Side w0.15: R118.2@114,114.6 114.1,114.7 v1(114.1,115.6)
SHIFT_REG_OE#: D11.51 D14.13 D15.13 R116.1 | length 186.1
  Component Side w0.15: D11.51@57.55,113.75 58.65,113.75 59,114.1 v1(59,114.5) ; D14.13@115.365,114.3 115.4,114.335 v1(115.4,115.6)
  Inner Layer 2 w0.15: v1(59,114.5) 59.7,113.8 59.7,113.4 60,113.1 61.9,113.1 62.2,113.4 62.2,114.1 61.3,115 61.3,116 62.1,116.8 63.2,116.8 64.4,118 88.5,118 89.2,118.7 90.3,118.7 92.1,116.9 114.1,116.9 v1(115.4,115.6)
  Solder Side w0.15: R116.1@115.3,114.6 115.4,114.7 v1(115.4,115.6) 116.9,117.1 121.8,117.1 122.5,117.8 207.7,117.8 208.7,116.8 229.1,116.8 230.635,115.265 D15.13@230.635,114.3
SRCLK: D11.53 D14.11 D15.11 R120.2 | length 180.9
  Component Side w0.15: D11.53@57.55,112.75 59.35,112.75 v1(60.4,113.8) ; v1(117.9,115.6) 117.9,114.305 D14.11@117.905,114.3
  Inner Layer 2 w0.15: v1(60.4,113.8) 60.4,114.4 60.5,114.5 60.5,116.4 61.7,117.6 62.8,117.6 64,118.8 88.1,118.8 88.8,119.5 90.631,119.5 92.431,117.7 114.5,117.7 115.5,116.7 116.2,116.7 116.6,116.3 117.2,116.3 v1(117.9,115.6)
  Solder Side w0.15: R120.2@117.9,114.6 v1(117.9,115.6) 118.6,116.3 122.2,116.3 122.9,117 207.3,117 208.3,116 227.29,116 228.095,115.195 D15.11@228.095,114.3
SW_MDC_1_W1: D9.W1 R225.1 | length 5.2
  Component Side w0.15: R225.1@76.6,60.25 76.95,59.9 79.7,59.9 80.1,59.5 D9.W1@81.5,59.5
SW_MDC_2_Y1: D9.Y1 R226.1 | length 7.8
  Component Side w0.15: R226.1@74.3,59.5 77.8,59.5 79,58.3 80,58.3 80.2,58.5 D9.Y1@81.5,58.5
SW_MDIO_1_W2: D9.W2 R111.1 | length 8.8
  Component Side w0.15: R111.1@74.3,61 77.1,61 77.8,60.3 80,60.3 80.3,60 82,60 D9.W2@82.5,59.5
SW_MDIO_2_Y3: D9.Y3 R227.1 | length 7.9
  Component Side w0.15: R227.1@76.6,58.8 77,58.8 v1(77.5,58.3) ; v10(83,59) D9.Y3@83.5,58.5
  Inner Layer 2 w0.15: v1(77.5,58.3) 77.9,57.9 80.3,57.9 81.4,59 v10(83,59)
TXLED#: D12.7 R12.2 | length 14.8
  Component Side w0.15: R12.2@45.4,125 46.1,124.3 48,124.3 48.3,124 49.4,124 50.6,122.8 56.2,122.8 v1(57.3,121.7)
  Solder Side w0.15: v1(57.3,121.7) 57.312,121.712 D12.7@57.312,123.276
USB_3.3V: C43.2 C57.2 C61.2 C63.2 D12.3 D12.10 D12.11 D12.12 L6.1 R9.2 R10.2 VD3.1 VD10.1 | length 47.1
  Component Side w0.2: v1(43.4,129.2) VD10.1@44.9,129.2 VD3.1@47.2,129.2 v1(48.7,129.2)
  Component Side w0.8: v1(62.8,123.2) 63.4,123.2 ; v1(63.4,124.1) 63.4,123.2 ; L6.1@65.35,123.2 v1(64,123.2) 63.4,123.2
  Inner Layer 2 w0.2: v1(43.4,129.2) v1(48.7,129.2)
  Inner Layer 2 w0.4: v1(48.7,129.2) 56.3,129.2 v1(57.6,127.9)
  Solder Side w0.15: R10.2@59.1,120.6 59.852,120.6 ; D12.3@59.852,123.276 59.852,120.6 ; R9.2@60.6,120.6 59.852,120.6
  Solder Side w0.3: C57.2@56.7,131.2 57.312,131.2 ; v1(57.6,127.9) 57.312,127.9 D12.10@57.312,129.524 57.312,131.2 ; v1@57.947,127.9 D12.11@57.947,129.524 C63.2@57.947,131.2 ; v1(58.6,127.9) 58.582,127.9 D12.12@58.582,129.524 58.582,131.2 ; C61.2@59.1,131.2 58.582,131.2 ; 57.312,131.2 C63.2@57.9,131.2 C63.2@57.947,131.2 ; C63.2@57.947,131.2 58.582,131.2
  Solder Side w0.35: D12.3@59.852,123.276 59.852,124.953 v1(59.9,125)
  Solder Side w0.8: v1@58.582,127.9 57.947,127.9 v1(57.6,127.9) v1(57.6,126.9) v1(58.6,126.9) v1(58.6,127.9) ; v1(59.9,125) v1(61,125)
USB_D_N: D12.9 R7.1 | length 9.3
  Component Side w0.22: R7.1@52.9,128.3 52.565,127.965 52.565,126.644 52.95,126.259 54.815,126.259 v11(55,126.444)
  Solder Side w0.22: v11(55,126.444) 55.185,126.259 56.4,126.259 56.677,126.536 D12.9@56.677,129.524
USB_D_P: D12.8 R8.1 | length 9.3
  Component Side w0.22: R8.1@51.8,128.3 52.135,127.965 52.135,126.466 52.772,125.829 54.815,125.829 v11(55,125.644)
  Solder Side w0.22: v11(55,125.644) 55.185,125.829 56.4,125.829 56.677,125.551 D12.8@56.677,123.276
X1_1_I2C_SCL: D16.5 R15.2 X1.29 | length 41.3
  Component Side w0.15: R15.2@78,88.1 v1(78,89.1) 78.315,89.415 X1.29@78.315,91.135 ; D16.5@85.9,109.465 86.765,109.465 v1(87.4,110.1)
  Inner Layer 1 w0.15: v1(87.4,110.1) 87.7,109.8 87.7,95.7 86.6,94.6 86.6,88.6 88.2,87 v1(88.7,87)
  Inner Layer 2 w0.15: v1(78,89.1) 80.1,87 v1(88.7,87)
X1_1_I2C_SDA: D16.4 R182.2 X1.31 | length 43.1
  Component Side w0.15: X1.31@78.815,91.135 78.815,89.785 79,89.6 79.2,89.6 v1(79.7,89.1) 79.1,88.5 R182.2@79.1,88.1 ; D16.4@85.9,110.735 86.835,110.735 87.1,111 v1(88.1,111)
  Inner Layer 1 w0.15: v1(88.1,111) 88.1,95.5 87,94.4 87,89 88.3,87.7 89.1,87.7 v1(89.8,87)
  Inner Layer 2 w0.15: v1(79.7,89.1) 80.3,88.5 81.5,88.5 82.3,87.7 89.1,87.7 v1(89.8,87)
X1_1_MDC_1: D5.8 X1.40 | length 23.3
  Component Side w0.2: v1(79.6,98.7) 80.3,98.7 80.815,98.185 X1.40@80.815,96.865
  Inner Layer 1 w0.17: v1(79.6,98.7) 78.9,99.4 78.9,102.2 81.2,104.5 v1(81.2,114.2)
  Solder Side w0.22: v1(81.2,114.2) D5.8@84.99,114.2
X1_1_SFP_PRES: D11.59 R13.2 X1.35 | length 52.2
  Component Side w0.15: v1(55.4,109.7) 55.45,109.75 D11.59@57.55,109.75 ; X1.35@79.815,91.135 79.815,89.885 80,89.7 80.2,89.7 80.5,89.4 80.5,88.4 R13.2@80.2,88.1 80.8,88.1 v1(81.2,87.7)
  Inner Layer 1 w0.15: v1(55.4,109.7) 55.4,109.2 56.5,108.1 56.5,101.7 58.1,100.1 v1(58.1,90.2)
  Inner Layer 2 w0.15: v1(58.1,90.2) 58.5,89.8 ; 58.2,89.8 78.3,89.8 78.9,89.2 78.9,88.8 80,87.7 v1(81.2,87.7)
X1_2_CON: R27.2 R39.1 X1.62 | length 4.6
  Component Side w0.15: R27.2@91,100.9 91.4,100.5 91.4,100.2 R39.1@91,99.8 91.395,99.405 91.395,98.195 91.32,98.12 X1.62@91.32,96.865
X1_2_COP: R28.2 R42.1 X1.64 | length 4.6
  Component Side w0.15: X1.64@91.82,96.865 91.82,98.08 91.705,98.195 91.705,99.405 R42.1@92.1,99.8 91.7,100.2 91.7,100.5 R28.2@92.1,100.9
X1_2_I2C_SCL: D16.10 R184.2 X1.89 | length 24.8
  Component Side w0.15: D16.10@91.7,106.925 92.075,106.925 92.5,106.5 v1(96.7,106.5) ; R184.2@98,87.7 98.32,88.02 X1.89@98.32,91.135 98.32,92.92 v1(98.4,93)
  Inner Layer 1 w0.15: v1(96.7,106.5) 96.7,98.2 97.9,97 97.9,93.5 v1(98.4,93)
X1_2_I2C_SDA: D16.9 R185.2 X1.91 | length 25.7
  Component Side w0.15: D16.9@91.7,105.655 92.055,105.655 92.5,106.1 96.1,106.1 96.5,105.7 v1(97.4,105.7) ; R185.2@99.1,87.7 98.82,87.98 X1.91@98.82,91.135 98.82,92.42 99.4,93 v1(99.4,93.2)
  Inner Layer 1 w0.15: v1(97.4,105.7) 97.1,105.4 97.1,98.3 98.3,97.1 98.3,95.4 99.4,94.3 v1(99.4,93.2) v1@99.4,93
X1_2_MDC_1: D5.11 X1.100 | length 31.9
  Component Side w0.2: v1(100.2,95) 100.82,95.62 X1.100@100.82,96.865
  Inner Layer 1 w0.17: v1(96.7,113.2) 96.7,107.6 98.2,106.1 98.2,100.5 99.7,99 99.7,95.5 v1(100.2,95)
  Inner Layer 2 w0.17: v1(88.2,112.9) 88.5,113.2 v1(96.7,113.2)
  Solder Side w0.22: v1(88.2,112.9) 88.6,113.3 88.6,114 D5.11@88.8,114.2
X1_2_SFP_PRES: D11.58 R183.2 X1.95 | length 78.6
  Component Side w0.15: v1(53.6,109.7) 54.3,109.7 55,110.4 55.8,110.4 55.95,110.25 D11.58@57.55,110.25 ; X1.95@99.82,91.135 99.82,89.78 100.2,89.4 R183.2@100.2,87.7 100.3,87.7 100.7,88.1 v1(101.2,88.1)
  Inner Layer 1 w0.15: v1(53.6,109.7) 53.9,109.4 53.9,108.8 55.3,107.4 55.3,101.1 56.9,99.5 56.9,92.2 55.9,91.2 v1(55.9,91)
  Inner Layer 2 w0.15: v1(55.9,91) 55.9,89.8 57.1,88.6 71,88.6 72.1,87.5 78.4,87.5 79.7,86.2 87.9,86.2 88.2,85.9 90.5,85.9 92,87.4 97.3,87.4 98,88.1 v1(101.2,88.1)
X2_1_MDC_1: D6.3 X2.40 | length 24.9
  Component Side w0.22: v1(136.8,95) 137.3,95 137.815,95.515 X2.40@137.815,96.865
  Inner Layer 1 w0.17: v1(136.8,95) 137.1,95.3 137.1,95.6 138.6,97.1 138.6,105.1 143.4,109.9 143.4,110.4 v1(144.2,111.2)
  Solder Side w0.22: v1(144.2,111.2) 144.2,114.17 D6.3@144.23,114.2
X2_2_CON: R29.2 R45.1 X2.62 | length 4.6
  Component Side w0.15: R29.2@148,100.9 148.4,100.5 148.4,100.2 R45.1@148,99.8 148.395,99.405 148.395,98.195 148.32,98.12 X2.62@148.32,96.865
X2_2_COP: R32.2 R48.1 X2.64 | length 4.6
  Component Side w0.15: X2.64@148.82,96.865 148.82,98.08 148.705,98.195 148.705,99.405 R48.1@149.1,99.8 148.7,100.2 148.7,100.5 R32.2@149.1,100.9
X2_2_MDC_1: D6.6 X2.100 | length 26.7
  Component Side w0.22: v1(157.1,94.9) 157.82,95.62 X2.100@157.82,96.865
  Inner Layer 1 w0.17: v1(151.4,112.8) 151.4,100.6 v1(157.1,94.9)
  Solder Side w0.22: D6.6@148.04,114.2 148.04,113.76 149,112.8 v1(151.4,112.8)
X3_1_CON: R14.2 X3.2 | length 3.1
  Solder Side w0.15: X3.2@162.815,96.865 162.815,98.085 162.705,98.195 162.705,99.405 R14.2@163.1,99.8
X3_1_COP: R16.2 X3.4 | length 3.1
  Solder Side w0.15: R16.2@162,99.8 162.395,99.405 162.395,98.195 162.315,98.115 X3.4@162.315,96.865
X3_1_MDC_1: D6.8 X3.40 | length 18.4
  Inner Layer 1 w0.17: v1(150.3,108.6) 150.9,108 150.9,100.4 154.1,97.2 v1(154.1,95)
  Solder Side w0.2: v1@154,95 v1(154.1,95)
  Solder Side w0.22: D6.8@149.31,108.6 v1(150.3,108.6) ; X3.40@153.315,96.865 153.315,95.685 v1@154,95
X3_2_CON: R25.2 R35.1 X3.62 | length 4.6
  Solder Side w0.15: X3.62@142.81,96.865 142.81,98.09 142.705,98.195 142.705,99.405 R35.1@143.1,99.8 142.7,100.2 142.7,100.5 R25.2@143.1,100.9
X3_2_COP: R26.2 R38.1 X3.64 | length 4.6
  Solder Side w0.15: R26.2@142,100.9 142.4,100.5 142.4,100.2 R38.1@142,99.8 142.395,99.405 142.395,98.195 142.31,98.11 X3.64@142.31,96.865
X3_2_MDC_1: D6.11 X3.100 | length 26.9
  Inner Layer 1 w0.17: v1(133.9,95) 135.7,95 136.5,94.2 137.1,94.2 137.6,94.7 137.6,95.5 139.1,97 139.1,104.9 v1(144.3,110.1)
  Solder Side w0.22: X3.100@133.31,96.865 133.31,95.59 v1(133.9,95) ; v1(144.3,110.1) 145,110.1 145.5,109.6 D6.11@145.5,108.6
X4_1_MDC_2: D7.3 X4.40 | length 23.8
  Component Side w0.22: v1(192.1,98.8) 194.2,98.8 194.815,98.185 X4.40@194.815,96.865
  Inner Layer 1 w0.17: v1(192.1,98.8) 192.6,98.8 195.1,101.3 195.1,104.5 201.4,110.8 v1(201.4,112)
  Solder Side w0.2: D7.3@201.4,114.17 D7.3@201.43,114.2
  Solder Side w0.22: v1(201.4,112) D7.3@201.4,114.17
X4_2_CON: R72.2 R78.1 X4.62 | length 4.6
  Component Side w0.15: R72.2@205,100.9 205.4,100.5 205.4,100.2 R78.1@205,99.8 205.4,99.4 205.4,98.2 205.32,98.12 X4.62@205.32,96.865
X4_2_COP: R73.2 R79.1 X4.64 | length 4.6
  Component Side w0.15: 205.71,99.4 205.71,98.19 205.82,98.08 X4.64@205.82,96.865 ; 205.71,99.41 R79.1@206.1,99.8 205.71,100.19 205.71,100.51 R73.2@206.1,100.9
X4_2_MDC_2: D7.6 X4.100 | length 24.2
  Component Side w0.22: v1(213.8,98.7) 214.4,98.7 214.82,98.28 X4.100@214.82,96.865
  Inner Layer 1 w0.17: v1(209.4,112.8) 210.2,112 210.2,101.1 212.6,98.7 v1(213.8,98.7)
  Solder Side w0.2: D7.6@205.24,113.76 D7.6@205.24,114.2
  Solder Side w0.22: D7.6@205.24,113.76 206.2,112.8 v1(209.4,112.8)
X5_1_CON: R66.2 X5.2 | length 3.1
  Solder Side w0.15: X5.2@219.815,96.865 219.815,98.085 219.705,98.195 219.705,99.405 R66.2@220.1,99.8
X5_1_COP: R67.2 X5.4 | length 3.1
  Solder Side w0.15: R67.2@219,99.8 219.395,99.405 219.395,98.195 219.315,98.115 X5.4@219.315,96.865
X5_1_MDC_2: D7.8 X5.40 | length 16.4
  Inner Layer 1 w0.17: v1(209.4,108.6) 209.7,108.3 209.7,100.5 v1(211.5,98.7)
  Solder Side w0.22: D7.8@206.51,108.6 v1(209.4,108.6) ; X5.40@210.315,96.865 210.315,98.215 210.8,98.7 v1(211.5,98.7)
X5_2_CON: R74.2 R80.1 X5.62 | length 4.6
  Solder Side w0.15: X5.62@199.81,96.865 199.81,98.09 199.705,98.195 199.705,99.405 R80.1@200.1,99.8 199.7,100.2 199.7,100.5 R74.2@200.1,100.9
X5_2_COP: R75.2 R81.1 X5.64 | length 4.6
  Solder Side w0.15: R75.2@199,100.9 199.4,100.5 199.4,100.2 R81.1@199,99.8 199.395,99.405 199.395,98.195 199.31,98.11 X5.64@199.31,96.865
X5_2_MDC_2: D7.11 X5.100 | length 22.5
  Inner Layer 1 w0.17: v1(191,98.8) 191.8,98 192.5,98 195.6,101.1 195.6,104.3 201.3,110 v1(202.7,110)
  Solder Side w0.22: X5.100@190.31,96.865 190.31,98.11 v1(191,98.8) ; D7.11@202.7,108.6 v1(202.7,110)
X6_1_MDC_2: D8.3 X6.40 | length 27.6
  Component Side w0.22: v1(250.6,98.7) 251.3,98.7 251.815,98.185 X6.40@251.815,96.865
  Inner Layer 1 w0.17: v1(250.6,98.7) 249.7,99.6 249.7,102.6 253.5,106.4 259.9,106.4 260.3,106.8 260.3,110.8 v1(258.3,112.8)
  Solder Side w0.2: D8.3@258.3,114.17 D8.3@258.33,114.2
  Solder Side w0.22: v1(258.3,112.8) D8.3@258.3,114.17
X6_2_CON: R76.2 R82.1 X6.62 | length 4.6
  Component Side w0.15: R76.2@262,100.9 262.4,100.5 262.4,100.2 R82.1@262,99.8 262.395,99.405 262.395,98.195 262.32,98.12 X6.62@262.32,96.865
X6_2_COP: R77.2 R83.1 X6.64 | length 4.6
  Component Side w0.15: X6.64@262.82,96.865 262.82,98.08 262.705,98.195 262.705,99.405 R83.1@263.1,99.8 262.7,100.2 262.7,100.5 R77.2@263.1,100.9
X6_2_MDC_2: D8.6 X6.100 | length 22.6
  Component Side w0.22: v1(270.8,98.7) 271.4,98.7 271.82,98.28 X6.100@271.82,96.865
  Inner Layer 1 w0.17: v1(262.1,112.8) 262.1,109.7 267.5,104.3 267.5,100.5 268.4,99.6 269.9,99.6 v1(270.8,98.7)
  Solder Side w0.22: v1(262.1,112.8) D8.6@262.1,114.16
X7_1_CON: R88.2 X7.2 | length 3.1
  Solder Side w0.15: X7.2@276.815,96.865 276.815,98.085 276.705,98.195 276.705,99.405 R88.2@277.1,99.8
X7_1_COP: R89.2 X7.4 | length 3.1
  Solder Side w0.15: R89.2@276,99.8 276.395,99.405 276.395,98.195 276.315,98.115 X7.4@276.315,96.865
X7_1_MDC_2: D8.8 X7.40 | length 15.2
  Inner Layer 1 w0.17: v1(263.4,107.2) 263.9,107.2 267,104.1 267,100.3 v1(268.6,98.7)
  Solder Side w0.22: v1(263.4,107.2) D8.8@263.4,108.59 ; X7.40@267.315,96.865 267.315,98.315 267.7,98.7 v1(268.6,98.7)
X7_2_CON: R98.2 R105.1 X7.62 | length 4.6
  Solder Side w0.15: X7.62@256.81,96.865 256.81,98.09 256.705,98.195 256.705,99.405 R105.1@257.1,99.8 256.7,100.2 256.7,100.5 R98.2@257.1,100.9
X7_2_COP: R99.2 R106.1 X7.64 | length 4.6
  Solder Side w0.15: R99.2@256,100.9 256.4,100.5 256.4,100.2 R106.1@256,99.8 256.395,99.405 256.395,98.195 256.31,98.11 X7.64@256.31,96.865
X7_2_MDC_2: D8.11 X7.100 | length 20.3
  Inner Layer 1 w0.17: v1(247.8,98.7) 249.2,100.1 249.2,102.8 253.3,106.9 259.3,106.9 v1(259.6,107.2)
  Solder Side w0.22: X7.100@247.31,96.865 247.31,98.21 v1(247.8,98.7) ; v1(259.6,107.2) D8.11@259.6,108.6
X8_1_CON: R90.2 X8.2 | length 3.1
  Solder Side w0.15: X8.2@105.815,96.865 105.815,98.085 105.705,98.195 105.705,99.405 R90.2@106.1,99.8
X8_1_COP: R91.2 X8.4 | length 3.1
  Solder Side w0.15: R91.2@105,99.8 105.395,99.405 105.395,98.195 105.315,98.115 X8.4@105.315,96.865
X8_1_I2C_SCL: D16.12 R230.2 X8.29 | length 39.6
  Component Side w0.15: v1(90,110.1) 90.635,109.465 D16.12@91.7,109.465
  Inner Layer 1 w0.15: v1(88.7,89.5) 87.8,90.4 87.8,94 88.9,95.1 88.9,109 v1(90,110.1)
  Inner Layer 2 w0.15: v1(88.7,89.5) 89.4,88.8 91.5,88.8 92.6,89.9 97.8,89.9 98.9,88.8 v1(99.5,88.8)
  Solder Side w0.15: X8.29@98.815,91.135 98.815,89.485 100,88.3 R230.2@100,87.9
X8_1_I2C_SDA: D16.11 R229.2 X8.31 | length 40.2
  Component Side w0.15: v1(88.9,110.1) 90.805,108.195 D16.11@91.7,108.195
  Inner Layer 1 w0.15: v1(88.7,88.4) 87.4,89.7 87.4,94.2 88.5,95.3 88.5,109.7 v1(88.9,110.1)
  Inner Layer 2 w0.15: v1(88.7,88.4) 88.9,88.2 96,88.2 96.8,89 v1(97.6,89)
  Solder Side w0.15: v1(97.6,89) 98.1,88.5 98.3,88.5 R229.2@99.1,87.7 ; v1@97.65,89.05 98.315,89.715 X8.31@98.315,91.135
X8_1_MDC_1: D5.3 X8.40 | length 20.5
  Inner Layer 1 w0.17: v1(95.7,105.4) 96.2,104.9 96.2,98 97.1,97.1 v1(97.1,95)
  Solder Side w0.22: D5.3@90.07,108.6 90.07,108.23 92.9,105.4 v1(95.7,105.4) ; X8.40@96.315,96.865 96.315,95.585 96.9,95 v1(97.1,95)
X8_1_SFP_PRES: D11.57 R228.2 X8.35 | length 74.9
  Component Side w0.15: v1(55.4,111.1) 55.9,111.1 56.25,110.75 D11.57@57.55,110.75
  Inner Layer 1 w0.15: v1(55.4,111.1) 54.7,111.8 54,111.8 53.6,111.4 53.6,110.8 54.3,110.1 54.3,109.1 55.7,107.7 55.7,101.3 57.3,99.7 57.3,92 56.6,91.3 v1(56.6,90.2)
  Inner Layer 2 w0.15: v1(56.6,90.2) 56.6,90 57.6,89 71.2,89 72.3,87.9 78.6,87.9 79.9,86.6 88.1,86.6 88.4,86.3 90.3,86.3 91.8,87.8 96.7,87.8 v1(97,88.1)
  Solder Side w0.15: X8.35@97.315,91.135 97.315,89.815 96.9,89.4 96.9,88.7 97,88.6 v1(97,88.1) 97.6,88.1 R228.2@98,87.7
X8_2_CON: R101.2 R107.1 X8.62 | length 4.6
  Solder Side w0.15: X8.62@85.81,96.865 85.8,96.875 85.8,98.1 85.705,98.195 85.705,99.405 R107.1@86.1,99.8 85.7,100.2 85.7,100.5 R101.2@86.1,100.9
X8_2_COP: R103.2 R108.1 X8.64 | length 4.6
  Solder Side w0.15: R103.2@85,100.9 85.4,100.5 85.4,100.2 R108.1@85,99.8 85.395,99.405 85.395,98.195 85.31,98.11 X8.64@85.31,96.865
X8_2_I2C_SCL: D16.7 R233.2 X8.89 | length 25.9
  Component Side w0.15: v1(80.5,106.9) 85.875,106.9 D16.7@85.9,106.925
  Inner Layer 1 w0.15: v11(78.9,92.9) 79.3,93.3 79.3,94.2 78.5,95 78.5,102.6 80.2,104.3 80.2,106.6 v1(80.5,106.9)
  Solder Side w0.15: v11(78.9,92.9) 78.81,92.81 X8.89@78.81,91.135 78.81,89.79 79.025,89.575 79.025,88.575 R233.2@79.5,88.1
X8_2_I2C_SDA: D16.6 R232.2 X8.91 | length 27.3
  Component Side w0.15: v1(79.8,107.7) 85,107.7 85.495,108.195 D16.6@85.9,108.195
  Inner Layer 1 w0.15: v11(78.1,92.9) 77.9,93.1 77.9,94.1 78.1,94.3 78.1,102.8 79.8,104.5 v1(79.8,107.7)
  Solder Side w0.15: v11(78.1,92.9) 78.31,92.69 X8.91@78.31,91.135 78.31,89.79 78.675,89.425 78.675,88.375 R232.2@78.4,88.1 R232.2@78.31,88.19
X8_2_MDC_1: D5.6 X8.100 | length 23.6
  Inner Layer 1 w0.17: v1(75.8,98.7) v1(75.8,108.6)
  Solder Side w0.2: v1(75.8,98.7) 76.31,98.19 X8.100@76.31,96.865
  Solder Side w0.22: v1(75.8,108.6) 80.6,108.6 81.7,109.7 85.6,109.7 86.26,109.04 D5.6@86.26,108.6
X8_2_SFP_PRES: D11.56 R231.2 X8.95 | length 50.6
  Component Side w0.15: v1(54.3,111.1) 55,111.8 56,111.8 56.55,111.25 D11.56@57.55,111.25
  Inner Layer 1 w0.15: v1(54.3,111.1) 54.7,110.7 54.7,109.3 56.1,107.9 56.1,101.5 57.7,99.9 57.7,91.3 v1(57.4,91)
  Inner Layer 2 w0.15: v1(57.4,91) 57.4,89.9 57.9,89.4 71.4,89.4 72.5,88.3 76.5,88.3 76.9,88.7 v1(76.9,89.1)
  Solder Side w0.15: R231.2@77.31,88.11 R231.2@77.3,88.1 76.9,88.5 v1(76.9,89.1) 77.31,89.51 X8.95@77.31,91.135
XTAL1_IN: D9.AC22 SA4.1 SA4.3 | length 25.9
  Component Side w0.25: D9.AC22@102.5,55.5 v10(103,56)
  Inner Layer 2 w0.17: v10(103,56) 104,55 105.4,55 105.7,54.7 112.9,54.7 114.8,52.8 v1(116.7,52.8) 116.7,52.7 117.9,51.5 120.8,51.5 121.9,52.6 v1(121.9,53.6)
  Solder Side w0.22: SA4.1@115.59,53.6 115.59,53.11 115.9,52.8 v1(116.7,52.8) ; SA4.3@120.67,53.6 v1(121.9,53.6)
XTAL2_OUT: D9.AB22 SA4.2 | length 20.4
  Component Side w0.25: D9.AB22@102.5,56.5 v10(103,57)
  Inner Layer 2 w0.17: v10(103,57) 103.5,56.5 104.5,56.5 105,57 113,57 113.3,57.3 115.7,57.3 v1(119.4,53.6)
  Solder Side w0.22: SA4.2@118.13,53.6 v1(119.4,53.6)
